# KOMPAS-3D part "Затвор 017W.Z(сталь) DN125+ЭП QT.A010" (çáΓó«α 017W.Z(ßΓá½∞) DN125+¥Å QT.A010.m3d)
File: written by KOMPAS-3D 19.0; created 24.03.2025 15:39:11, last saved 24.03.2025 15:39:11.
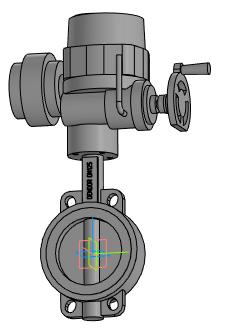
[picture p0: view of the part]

Document properties: Полное имя файла: Затвор 017W.Z(сталь) DN125+ЭП QT.A010.a3d

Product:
- Part/product: Затвор 017W.Z(сталь) DN125+ЭП QT.A010
    Масса: 45.3381

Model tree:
1. Операция без истории:1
